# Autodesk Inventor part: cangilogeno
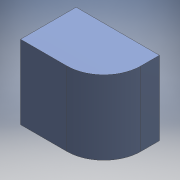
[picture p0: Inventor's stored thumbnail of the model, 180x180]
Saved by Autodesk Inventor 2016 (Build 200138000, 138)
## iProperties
Created: 2016-06
Part Number: cangilogeno
Material: Genérico
Document SubType Name: Modeling
Designer: adm
Density: 1 g/cm^3
Appearance: Valor por defecto
Author: adm
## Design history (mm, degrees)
sketch "Boceto1"
  geometry: L1 (22.5, 15)-(-22.5, 15); L2 (-22.5, 15)-(-22.5, -15); L3 (-22.5, -15)-(2.5, -15); L4 (22.5, 5)-(22.5, 15); L5 (22.5, 15)-(-22.5, -15); L6 (-22.5, 15)-(22.5, -15); A1 r 20 centre (2.5, 5) between (2.5, -15) and (22.5, 5); 1 further point
  constraints: 12 end point, 2 midpoint, 2 parallel, 2 point on circle, 2 point on line, 2 tangent, 1 centre point, 1 horizontal, 1 perpendicular
  dimensions: "d0" = 45 distance of L6.end L2.end; "d1" = 30 distance of L2.end L1.end; "d2" = 20 radius of A1
extrude "Extrusión1" new body sketch "Boceto1" distance "d3" = 40; taper "d4" = 0 deg
feature "Vaciado1" dims "d5" = 3
node "Sólido1"
